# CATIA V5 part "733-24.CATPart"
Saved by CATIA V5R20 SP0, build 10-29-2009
Part number: 733-24
Bounding box of the stored display mesh (mm): x -24 to 24, y -23.94 to 23.94, z -23 to 56
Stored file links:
  C:\Users\Utente\Desktop\IO LAVORO\3D X SITO CF\X SITO\733\733-24.CATPart
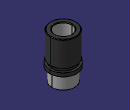
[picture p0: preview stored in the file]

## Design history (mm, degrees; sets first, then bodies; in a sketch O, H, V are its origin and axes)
Set1
  DatumSurface1 to DatumSurface25 "733-24"
Body1 (main body)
